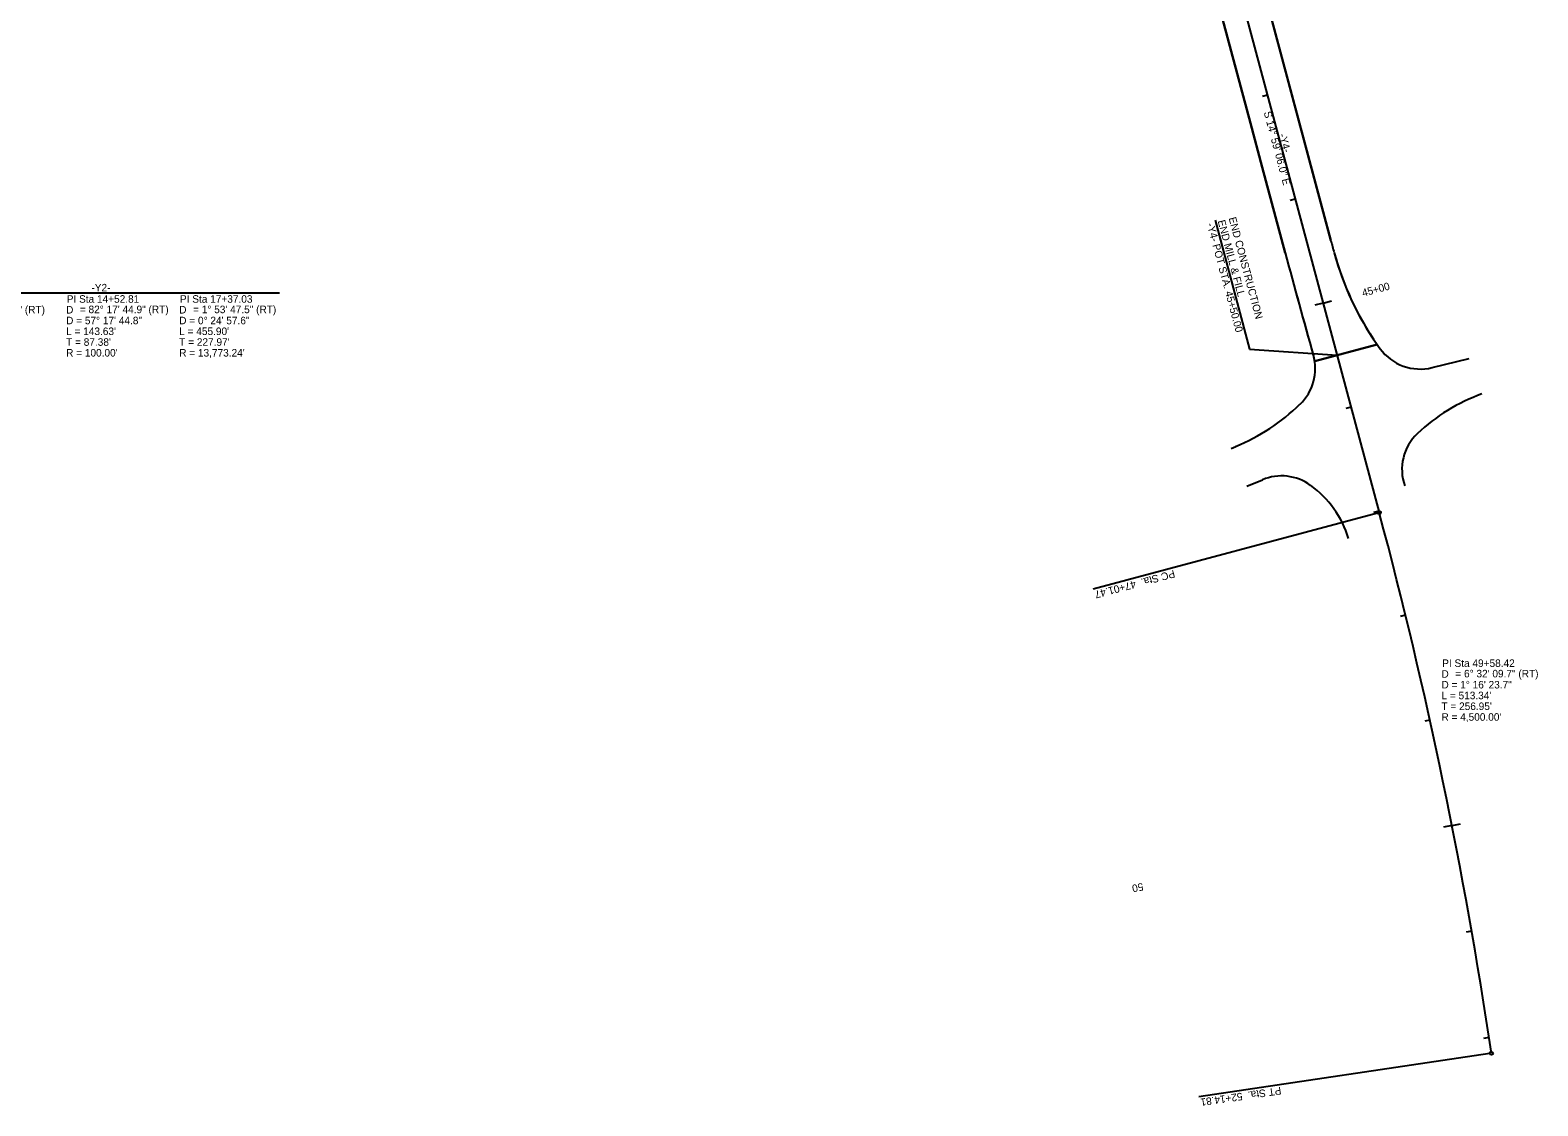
# Model space of a CAD drawing. Extents: x 1616561 to 1622460, y 896726 to 899651.
# Drawn here: x 1620474 to 1621875, y 896726 to 897726 of the extents above; entities that cross this region are included whole.
import ezdxf

# ---------------------------------------------------------------- set-up
doc = ezdxf.new("R2010")
doc.units = 0
for name, color, linetype in [('Old_Level_40', 7, 'Continuous'), ('Prop Dimension', 7, 'Continuous'), ('Prop Horizontal Alignment', 7, 'Continuous'), ('Prop Shade Light', 7, 'Continuous'), ('Prop Superelevation  Arrow CELL', 7, 'Continuous'), ('Prop Superelevation Label', 7, 'Continuous'), ('Prop Terminator CELL', 7, 'Continuous'), ('Scratch_Level_1', 7, 'Continuous'), ('Sheet Cutting Line CELL', 7, 'Continuous'), ('Sheet North Arrow CELL', 7, 'Continuous'), ('Sheet Sticker Incomplete CELL', 7, 'Continuous')]:
    doc.layers.add(name, color=color, linetype=linetype)

msp = doc.modelspace()

# ---------------------------------------------------------------- linework, layer by layer
at = {"layer": 'Old_Level_40'}
for p, q in [((1621601, 897835.2), (1621682.6, 897530.1)), ((1621607.9, 897639.3), (1621577.6, 897752.4)), ((1621618.8, 897598.4), (1621607.9, 897639.3)), ((1621640.1, 897518.7), (1621618.8, 897598.4)), ((1621725.5, 897433.7), (1621667.5, 897418.1))]:
    msp.add_line(p, q, dxfattribs=at)
for centre, radius, start, end in [((1628635.8, 899391.3), 7198, 194.98501, 195.07703), ((1628635.8, 899391.3), 7242, 194.98501, 195.76723), ((1621947.3, 897589.4), 271, 195.077, 215.0802), ((1621622, 897411.2), 46, 8.6431, 15.7646)]:
    msp.add_arc(centre, radius, start, end, dxfattribs=at)
at = {"layer": 'Prop Horizontal Alignment'}
for p, q in [((1621601, 897835.2), (1621682.6, 897530.1)), ((1621577.6, 897752.4), (1621607.9, 897639.3)), ((1621618.8, 897598.4), (1621640.1, 897518.7)), ((1621776.6, 897412.2), (1621811.1, 897420.7)), ((1621589.9, 897337), (1621594.1, 897338.7)), ((1621604.6, 897301.9), (1621618.9, 897307.9))]:
    msp.add_line(p, q, dxfattribs=at)
for centre, radius, start, end in [((1628635.8, 899391.3), 7198, 194.98501, 195.07703), ((1628635.8, 899391.3), 7242, 194.98501, 195.76723), ((1621947.3, 897589.4), 271, 195.077, 216.1165), ((1621622, 897411.2), 46, 313.8577, 15.7646), ((1621765.5, 897456.8), 46, 216.1165, 283.9624), ((1621518, 897519.4), 196, 292.8183, 313.8577), ((1621880.6, 897226.7), 171, 109.6998, 133.468), ((1621794.6, 897317.5), 46, 133.468, 199.421), ((1621636.7, 897265.5), 46, 53.9991, 112.8183), ((1621607.3, 897225.1), 96, 17.1292, 53.9991)]:
    msp.add_arc(centre, radius, start, end, dxfattribs=at)
at = {"layer": 'Prop Shade Light'}
for p, q in [((1621682.6, 897530.1), (1621601, 897835.2)), ((1621577.6, 897752.4), (1621607.9, 897639.3)), ((1621607.9, 897639.3), (1621618.8, 897598.4)), ((1621618.8, 897598.4), (1621640.1, 897518.7)), ((1621667.5, 897418.1), (1621725.5, 897433.7))]:
    msp.add_line(p, q, dxfattribs=at)
for centre, radius, start, end in [((1628635.8, 899391.3), 7198, 194.98501, 195.07703), ((1628635.8, 899391.3), 7242, 194.98501, 195.76455), ((1621947.3, 897589.4), 271, 195.077, 215.0802), ((1621622, 897411.2), 46, 8.6431, 15.7646)]:
    msp.add_arc(centre, radius, start, end, dxfattribs=at)
at = {"layer": 'Prop Superelevation  Arrow CELL'}
for p, q in [((1621623.7, 897665.2), (1621618.9, 897663.9)), ((1621649.5, 897568.6), (1621644.7, 897567.3)), ((1621701.3, 897375.4), (1621696.4, 897374.1)), ((1621727.1, 897278.8), (1621722.3, 897277.5)), ((1621751.9, 897182), (1621747.1, 897180.8)), ((1621774.6, 897084.6), (1621769.7, 897083.5)), ((1621813.4, 896888.4), (1621808.4, 896887.5)), ((1621829.5, 896789.7), (1621824.5, 896788.9))]:
    msp.add_line(p, q, dxfattribs=at)
at = {"layer": 'Prop Superelevation Label'}
for p, q in [((1621675.4, 897472), (1621683.1, 897474.1)), ((1621675.4, 897472), (1621667.7, 897470)), ((1621795.1, 896986.7), (1621787.2, 896985.1)), ((1621795.1, 896986.7), (1621802.9, 896988.2))]:
    msp.add_line(p, q, dxfattribs=at)
at = {"layer": 'Prop Terminator CELL'}
msp.add_line((1621725.5, 897433.7), (1621667.5, 897418.1), dxfattribs=at)
at = {"layer": 'Sheet Cutting Line CELL'}
msp.add_line((1621287.6, 898921), (1621727.5, 897277.4), dxfattribs=at)
msp.add_arc((1617380.5, 896113.9), 4500, 8.449, 14.985, dxfattribs=at)
at = {"layer": 'Sheet North Arrow CELL'}
for p, q in [((1621574.9, 897549.1), (1621606.9, 897429.3)), ((1621606.9, 897429.3), (1621688.3, 897423.7)), ((1621726, 897277), (1621461.8, 897206.3)), ((1621830.2, 896774.8), (1621559.7, 896734.6))]:
    msp.add_line(p, q, dxfattribs=at)
for centre in [(1621727.5, 897277.4), (1621831.7, 896775)]:
    msp.add_circle(centre, 1.5, dxfattribs=at)
at = {"layer": 'Sheet Sticker Incomplete CELL'}
msp.add_line((1620391.4, 897481.6), (1620705.5, 897481.6), dxfattribs=at)

# ---------------------------------------------------------------- texts
at = {"layer": 'Prop Dimension'}
for s, rotation, p in [('45+00', 14.985, (1621712.5, 897478)), ('50', 191.1841, (1621507.5, 896933.4))]:
    msp.add_text(s, height=7, rotation=rotation, dxfattribs=at).set_placement(p)
at = {"layer": 'Scratch_Level_1'}
for s, rotation, p in [('S 14%%d 59\' 06.0" E', 284.985, (1621620.1, 897649.3)), ('-Y4-', 284.9555, (1621634.2, 897628.5))]:
    msp.add_text(s, height=7, rotation=rotation, dxfattribs=at).set_placement(p)
at = {"layer": 'Sheet North Arrow CELL'}
for s, rotation, p in [('-Y4- POT STA. 45+50.00', 284.985, (1621567.2, 897545.6)), ('END MILL & FILL', 284.985, (1621577.3, 897548.3)), ('END CONSTRUCTION', 284.985, (1621587.5, 897551)), ('PC Sta.  47+01.47', 194.985, (1621536.6, 897224.2)), ('PT Sta.  52+14.81', 188.449, (1621635.9, 896743.9))]:
    msp.add_text(s, height=7, rotation=rotation, dxfattribs=at).set_placement(p)
at = {"layer": 'Sheet Sticker Incomplete CELL'}
for s, p in [('-Y2-', (1620530.8, 897482.9)), ('PI Sta 14+52.81', (1620507.9, 897472.4)), ('PI Sta 17+37.03', (1620613.1, 897472.4)), ('= 73%%d 24\' 43.2" (RT)', (1620405.2, 897462.5)), ('D', (1620507.3, 897462.4)), ('D = 57%%d 17\' 44.8"', (1620507.3, 897452.4)), ('= 82%%d 17\' 44.9" (RT)', (1620520.1, 897462.7)), ('D', (1620612.4, 897462.4)), ('D = 0%%d 24\' 57.6"', (1620612.4, 897452.4)), ('= 1%%d 53\' 47.5" (RT)', (1620625.3, 897462.7)), ("L = 143.63'", (1620507.3, 897442.4)), ("L = 455.90'", (1620612.4, 897442.4)), ("T = 87.38'", (1620507.3, 897432.4)), ("T = 227.97'", (1620612.4, 897432.4)), ("R = 100.00'", (1620507.3, 897422.4)), ("R = 13,773.24'", (1620612.4, 897422.4)), ('PI Sta 49+58.42', (1621786, 897134)), ('D', (1621785.3, 897124)), ('= 6%%d 32\' 09.7" (RT)', (1621798.2, 897124.3)), ('D = 1%%d 16\' 23.7"', (1621785.3, 897114)), ("L = 513.34'", (1621785.3, 897104)), ("T = 256.95'", (1621785.3, 897094)), ("R = 4,500.00'", (1621785.3, 897084))]:
    msp.add_text(s, height=7, dxfattribs=at).set_placement(p)

doc.saveas('drawing.dxf')
